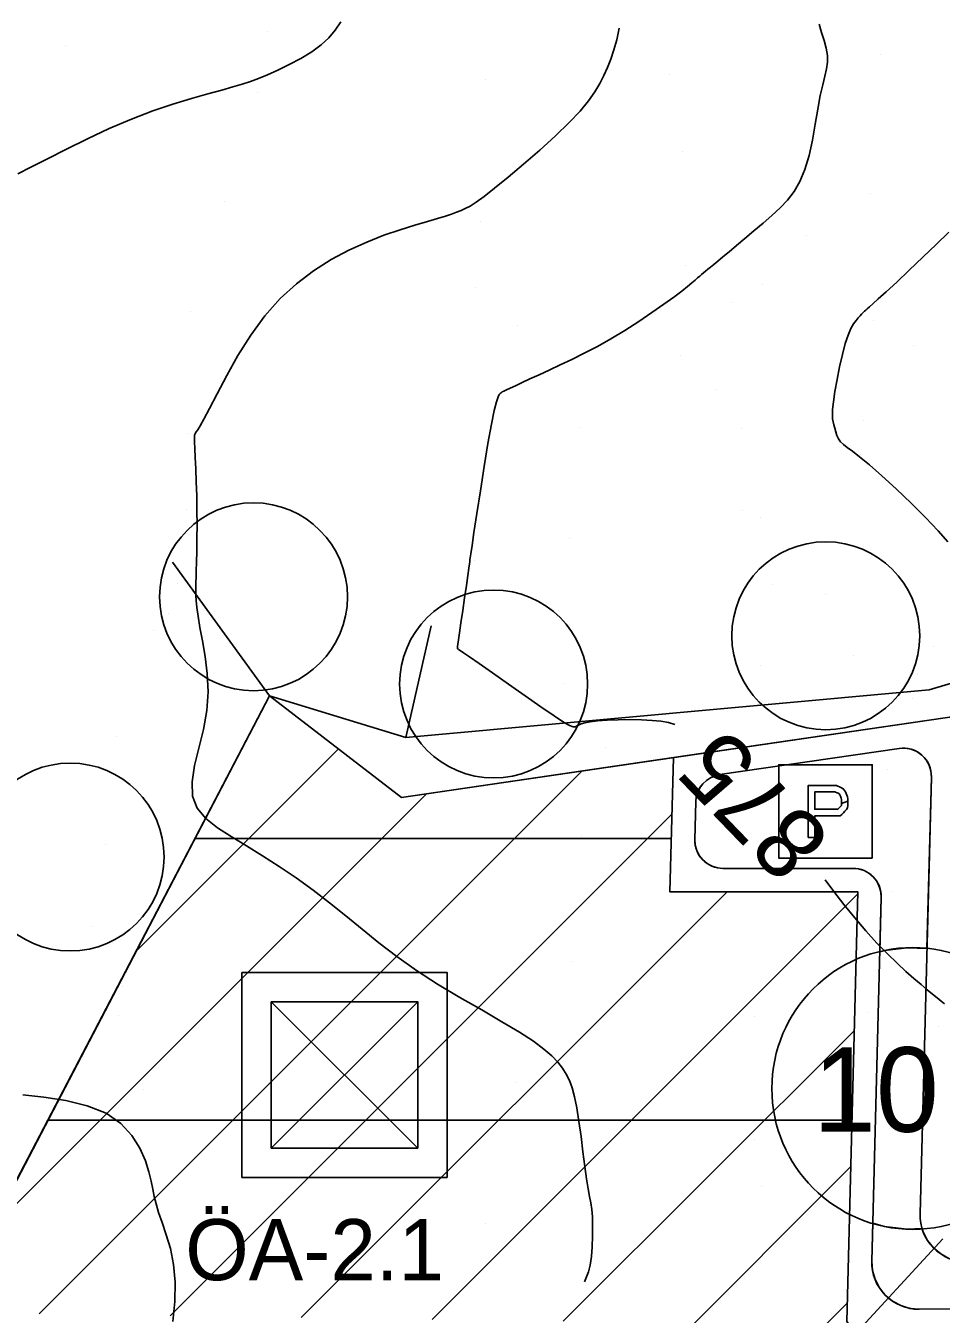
# Model space of a CAD drawing. Extents: x 400243 to 403697, y 4403637 to 4408083.
# Drawn here: x 402609.9 to 402707.4, y 4406077.2 to 4406214.4 of the extents above; entities that cross this region are included whole.
import ezdxf

# ---------------------------------------------------------------- set-up
doc = ezdxf.new("R2010")
doc.units = 0
for name, color, linetype in [('ADAKENARI', 7, 'Continuous'), ('HH_IC', 7, 'Continuous'), ('KALDIRIM', 7, 'Continuous'), ('PL_GES', 7, 'Continuous'), ('PL_YAZI', 7, 'Continuous'), ('PL_YOL', 7, 'Continuous'), ('SM_DAIRE', 7, 'Continuous'), ('SM_SEMBOL', 7, 'Continuous'), ('SM_YGEN', 7, 'Continuous'), ('SNR_MULKIYET', 7, 'Continuous'), ('SNR_ONAMA', 7, 'Continuous'), ('SNR_SEMBOL', 7, 'Continuous'), ('TR_GES', 7, 'Continuous')]:
    doc.layers.add(name, color=color, linetype=linetype)

msp = doc.modelspace()

# ---------------------------------------------------------------- linework, layer by layer
at = {"layer": 'ADAKENARI'}
for p, q in [((402560.49, 4405998.76), (402635.88, 4406143.05)), ((402635.88, 4406143.05), (402649.95, 4406132.25)), ((402678.87, 4406136.48), (402709, 4406140.88)), ((402649.95, 4406132.25), (402678.87, 4406136.48)), ((402678.87, 4406136.48), (402678.5, 4406122.19)), ((402678.5, 4406122.19), (402698.51, 4406122.19)), ((402698.51, 4406122.19), (402697.33, 4406076.45))]:
    msp.add_line(p, q, dxfattribs=at)
at = {"layer": 'HH_IC'}
for p, q in [((402635.66, 4406213.79), (402635.66, 4406213.79)), ((402614.19, 4406212.31), (402614.19, 4406212.31)), ((402700.92, 4406211.39), (402700.92, 4406211.39)), ((402658.88, 4406208.7), (402658.88, 4406208.7)), ((402678.51, 4406209.24), (402678.51, 4406209.24)), ((402634.62, 4406207.26), (402634.62, 4406207.26)), ((402679.87, 4406201), (402679.87, 4406201)), ((402699.88, 4406196.49), (402699.88, 4406196.49)), ((402631.11, 4406195.7), (402631.11, 4406195.7)), ((402658.31, 4406193.53), (402658.31, 4406193.53)), ((402693.03, 4406192.06), (402693.03, 4406192.06)), ((402680.15, 4406188.84), (402680.15, 4406188.84)), ((402688.4, 4406186.9), (402688.4, 4406186.9)), ((402657.78, 4406186.51), (402657.78, 4406186.51)), ((402627.45, 4406183.96), (402627.45, 4406183.96)), ((402685.09, 4406184.9), (402685.09, 4406184.9)), ((402700.19, 4406183.01), (402700.19, 4406183.01)), ((402662.24, 4406182.45), (402662.24, 4406182.45)), ((402704.38, 4406180.41), (402704.38, 4406180.41)), ((402679.59, 4406179.28), (402679.59, 4406179.28)), ((402660.65, 4406174.81), (402660.65, 4406174.81)), ((402683.48, 4406175.67), (402683.48, 4406175.67)), ((402669.02, 4406171.6), (402669.02, 4406171.6)), ((402699.11, 4406172.34), (402699.11, 4406172.34)), ((402627.31, 4406170.94), (402627.31, 4406170.94)), ((402686.1, 4406171.54), (402686.1, 4406171.54)), ((402627.02, 4406162.93), (402627.02, 4406162.93)), ((402686.28, 4406162.75), (402686.28, 4406162.75)), ((402688.19, 4406162.1), (402688.19, 4406162.1)), ((402667.84, 4406159.77), (402667.84, 4406159.77)), ((402657.67, 4406157.43), (402657.67, 4406157.43)), ((402626.06, 4406155.05), (402626.06, 4406155.05)), ((402689.4, 4406154.94), (402689.4, 4406154.94)), ((402695.11, 4406153.89), (402695.11, 4406153.89)), ((402625.18, 4406151.84), (402625.18, 4406151.84)), ((402623.55, 4406150.06), (402623.55, 4406150.06)), ((402706.57, 4406148.32), (402706.57, 4406148.32)), ((402656.08, 4406148.2), (402656.08, 4406148.2)), ((402698.07, 4406147.37), (402698.07, 4406147.37)), ((402688.15, 4406146.3), (402688.15, 4406146.3)), ((402667.24, 4406144.39), (402667.24, 4406144.39)), ((402704.88, 4406145.3), (402704.88, 4406145.3)), ((402704.32, 4406142.82), (402704.32, 4406142.82)), ((402689.66, 4406142.33), (402689.66, 4406142.33)), ((402619.62, 4406138.75), (402619.62, 4406138.75)), ((402668.07, 4406139.97), (402668.07, 4406139.97)), ((402671.7, 4406137.54), (402671.7, 4406137.54)), ((402690.86, 4406135.65), (402690.86, 4406135.65)), ((402701.68, 4406135.24), (402701.68, 4406135.24)), ((402669.04, 4406128.11), (402669.04, 4406128.11)), ((402618.41, 4406127.28), (402618.41, 4406127.28)), ((402689.5, 4406125.46), (402689.5, 4406125.46)), ((402702.05, 4406122.2), (402702.05, 4406122.2)), ((402616.97, 4406118.46), (402616.97, 4406118.46)), ((402668.06, 4406114.78), (402668.06, 4406114.78)), ((402620.2, 4406112.09), (402620.2, 4406112.09)), ((402619.87, 4406109.06), (402619.87, 4406109.06)), ((402687.46, 4406108.95), (402687.46, 4406108.95)), ((402699.51, 4406109.33), (402699.51, 4406109.33)), ((402707.11, 4406107.84), (402707.11, 4406107.84)), ((402662.12, 4406101.95), (402662.12, 4406101.95)), ((402622.46, 4406101.16), (402622.46, 4406101.16)), ((402687.52, 4406095.78), (402687.52, 4406095.78)), ((402705.6, 4406095.41), (402705.6, 4406095.41)), ((402625.36, 4406091.26), (402625.36, 4406091.26)), ((402688.23, 4406090.81), (402688.23, 4406090.81)), ((402658.83, 4406086.89), (402658.83, 4406086.89)), ((402705.48, 4406084.27), (402705.48, 4406084.27)), ((402628.32, 4406082.21), (402628.32, 4406082.21))]:
    msp.add_line(p, q, dxfattribs=at)
for points in [[(402609.09, 4406198.63), (402610.5, 4406199.34), (402612.25, 4406200.24), (402614.28, 4406201.27), (402616.51, 4406202.37), (402618.84, 4406203.47), (402621.19, 4406204.47), (402623.46, 4406205.34), (402625.6, 4406206.07), (402627.57, 4406206.67), (402629.32, 4406207.16), (402630.8, 4406207.56), (402632, 4406207.89), (402632.98, 4406208.18), (402633.85, 4406208.47), (402634.71, 4406208.79), (402635.66, 4406209.18), (402636.77, 4406209.67), (402637.99, 4406210.26), (402639.22, 4406210.91), (402640.39, 4406211.62), (402641.4, 4406212.36), (402642.21, 4406213.12), (402642.87, 4406213.94), (402643.49, 4406214.83)], [(402669.42, 4406080.69), (402669.64, 4406081.19), (402669.84, 4406081.74), (402670.02, 4406082.45), (402670.15, 4406083.36), (402670.24, 4406084.41), (402670.28, 4406085.53), (402670.28, 4406086.61), (402670.25, 4406087.58), (402670.18, 4406088.37), (402670.07, 4406089.07), (402669.94, 4406089.77), (402669.79, 4406090.59), (402669.62, 4406091.64), (402669.44, 4406092.97), (402669.24, 4406094.52), (402669.04, 4406096.15), (402668.82, 4406097.75), (402668.59, 4406099.19), (402668.36, 4406100.37), (402668.1, 4406101.32), (402667.8, 4406102.11), (402667.46, 4406102.79), (402667.06, 4406103.42), (402666.57, 4406104.05), (402665.95, 4406104.72), (402665.1, 4406105.45), (402663.98, 4406106.29), (402662.5, 4406107.25), (402660.63, 4406108.37), (402658.47, 4406109.62), (402656.14, 4406110.96), (402653.78, 4406112.38), (402651.52, 4406113.83), (402649.44, 4406115.3), (402647.54, 4406116.76), (402645.75, 4406118.21), (402644.02, 4406119.64), (402642.29, 4406121.03), (402640.52, 4406122.38), (402638.73, 4406123.67), (402636.93, 4406124.89), (402635.16, 4406126.04), (402633.44, 4406127.1), (402631.81, 4406128.07), (402630.34, 4406129.01), (402629.1, 4406130), (402628.2, 4406131.09), (402627.69, 4406132.38), (402627.64, 4406133.9), (402627.92, 4406135.63), (402628.38, 4406137.5), (402628.87, 4406139.48), (402629.23, 4406141.49), (402629.35, 4406143.5), (402629.26, 4406145.44), (402629.04, 4406147.26), (402628.75, 4406148.92), (402628.48, 4406150.35), (402628.29, 4406151.53), (402628.16, 4406152.46), (402628.08, 4406153.2), (402628.05, 4406153.76), (402628.04, 4406154.19), (402628.04, 4406154.52), (402628.04, 4406154.83), (402628.06, 4406155.19), (402628.08, 4406155.67), (402628.1, 4406156.36), (402628.13, 4406157.3), (402628.15, 4406158.46), (402628.17, 4406159.8), (402628.18, 4406161.26), (402628.17, 4406162.79), (402628.14, 4406164.34), (402628.09, 4406165.84), (402628.04, 4406167.23), (402627.98, 4406168.44), (402627.94, 4406169.41), (402627.92, 4406170.1), (402627.91, 4406170.55), (402627.92, 4406170.81), (402627.96, 4406170.96), (402628.02, 4406171.05), (402628.1, 4406171.16), (402628.25, 4406171.38), (402628.51, 4406171.8), (402628.91, 4406172.53), (402629.5, 4406173.65), (402630.31, 4406175.23), (402631.33, 4406177.16), (402632.53, 4406179.29), (402633.89, 4406181.45), (402635.4, 4406183.52), (402637.04, 4406185.35), (402638.77, 4406186.94), (402640.58, 4406188.32), (402642.44, 4406189.51), (402644.33, 4406190.52), (402646.23, 4406191.37), (402648.07, 4406192.09), (402649.8, 4406192.68), (402651.37, 4406193.17), (402652.7, 4406193.56), (402653.77, 4406193.88), (402654.61, 4406194.13), (402655.27, 4406194.35), (402655.8, 4406194.54), (402656.27, 4406194.73), (402656.72, 4406194.93), (402657.24, 4406195.21), (402657.88, 4406195.63), (402658.72, 4406196.24), (402659.84, 4406197.12), (402661.28, 4406198.28), (402662.93, 4406199.67), (402664.65, 4406201.17), (402666.31, 4406202.68), (402667.78, 4406204.09), (402668.95, 4406205.32), (402669.84, 4406206.4), (402670.52, 4406207.35), (402671.05, 4406208.24), (402671.48, 4406209.09), (402671.87, 4406209.95), (402672.22, 4406210.85), (402672.55, 4406211.83), (402672.84, 4406212.91), (402673.11, 4406214.13)], [(402679.04, 4406140), (402678.35, 4406140.21), (402677.55, 4406140.36), (402676.61, 4406140.45), (402675.49, 4406140.51), (402674.26, 4406140.53), (402673.01, 4406140.52), (402671.83, 4406140.48), (402670.81, 4406140.41), (402670.03, 4406140.31), (402669.45, 4406140.19), (402669.04, 4406140.07), (402668.76, 4406139.95), (402668.57, 4406139.84), (402668.41, 4406139.75), (402668.19, 4406139.75), (402667.82, 4406139.9), (402667.18, 4406140.27), (402666.19, 4406140.92), (402664.78, 4406141.88), (402663.09, 4406143.05), (402661.31, 4406144.3), (402659.61, 4406145.5), (402658.19, 4406146.5), (402657.18, 4406147.21), (402656.54, 4406147.65), (402656.18, 4406147.9), (402656.01, 4406148.01), (402655.95, 4406148.05), (402655.91, 4406148.08), (402655.9, 4406148.1), (402655.89, 4406148.12), (402655.89, 4406148.13), (402655.89, 4406148.15), (402655.89, 4406148.16), (402655.89, 4406148.18), (402655.89, 4406148.19), (402655.89, 4406148.2), (402655.89, 4406148.21), (402655.89, 4406148.23), (402655.9, 4406148.32), (402655.93, 4406148.56), (402656, 4406149.01), (402656.11, 4406149.76), (402656.26, 4406150.84), (402656.45, 4406152.13), (402656.65, 4406153.51), (402656.84, 4406154.81), (402657, 4406155.89), (402657.11, 4406156.65), (402657.17, 4406157.12), (402657.21, 4406157.37), (402657.22, 4406157.48), (402657.22, 4406157.51), (402657.22, 4406157.56), (402657.25, 4406157.74), (402657.31, 4406158.19), (402657.44, 4406159.05), (402657.65, 4406160.46), (402657.96, 4406162.47), (402658.33, 4406164.9), (402658.74, 4406167.47), (402659.14, 4406169.91), (402659.5, 4406171.97), (402659.8, 4406173.43), (402660.03, 4406174.36), (402660.21, 4406174.89), (402660.34, 4406175.15), (402660.45, 4406175.26), (402660.55, 4406175.33), (402660.66, 4406175.41), (402660.83, 4406175.5), (402661.1, 4406175.63), (402661.5, 4406175.82), (402662.06, 4406176.08), (402662.77, 4406176.42), (402663.61, 4406176.81), (402664.58, 4406177.25), (402665.66, 4406177.75), (402666.82, 4406178.29), (402668.07, 4406178.88), (402669.39, 4406179.53), (402670.78, 4406180.26), (402672.22, 4406181.07), (402673.71, 4406181.97), (402675.18, 4406182.92), (402676.58, 4406183.86), (402677.85, 4406184.75), (402678.93, 4406185.52), (402679.76, 4406186.15), (402680.39, 4406186.64), (402680.85, 4406187.02), (402681.18, 4406187.31), (402681.44, 4406187.55), (402681.67, 4406187.75), (402681.87, 4406187.92), (402682.07, 4406188.09), (402682.29, 4406188.27), (402682.53, 4406188.47), (402682.82, 4406188.71), (402683.16, 4406189), (402683.6, 4406189.35), (402684.13, 4406189.8), (402684.8, 4406190.34), (402685.59, 4406191), (402686.49, 4406191.75), (402687.44, 4406192.55), (402688.41, 4406193.38), (402689.35, 4406194.2), (402690.22, 4406195.01), (402691.01, 4406195.84), (402691.72, 4406196.76), (402692.34, 4406197.82), (402692.87, 4406199.08), (402693.31, 4406200.58), (402693.67, 4406202.23), (402693.97, 4406203.92), (402694.25, 4406205.53), (402694.5, 4406206.96), (402694.76, 4406208.11), (402694.99, 4406209.04), (402695.18, 4406209.82), (402695.28, 4406210.52), (402695.27, 4406211.23), (402695.14, 4406212.01), (402694.92, 4406212.83), (402694.65, 4406213.7), (402694.39, 4406214.58)], [(402708.09, 4406159.44), (402707.04, 4406160.63), (402705.7, 4406162.04), (402704.17, 4406163.56), (402702.59, 4406165.09), (402701.07, 4406166.49), (402699.74, 4406167.66), (402698.69, 4406168.52), (402697.92, 4406169.1), (402697.36, 4406169.5), (402696.96, 4406169.81), (402696.67, 4406170.09), (402696.45, 4406170.42), (402696.28, 4406170.79), (402696.15, 4406171.18), (402696.04, 4406171.56), (402695.96, 4406171.92), (402695.88, 4406172.23), (402695.82, 4406172.56), (402695.79, 4406172.98), (402695.81, 4406173.56), (402695.9, 4406174.37), (402696.06, 4406175.46), (402696.29, 4406176.74), (402696.56, 4406178.09), (402696.86, 4406179.4), (402697.17, 4406180.56), (402697.48, 4406181.47), (402697.77, 4406182.16), (402698.05, 4406182.67), (402698.31, 4406183.03), (402698.54, 4406183.31), (402698.74, 4406183.53), (402698.91, 4406183.71), (402699.06, 4406183.86), (402699.21, 4406184), (402699.35, 4406184.13), (402699.51, 4406184.27), (402699.75, 4406184.47), (402700.11, 4406184.8), (402700.68, 4406185.32), (402701.51, 4406186.08), (402702.64, 4406187.12), (402703.98, 4406188.38), (402705.42, 4406189.75), (402706.85, 4406191.13), (402708.17, 4406192.43)], [(402707.74, 4406110.28), (402707.36, 4406110.56), (402706.94, 4406110.9), (402706.45, 4406111.3), (402705.88, 4406111.77), (402705.23, 4406112.32), (402704.47, 4406112.97), (402703.62, 4406113.72), (402702.68, 4406114.59), (402701.65, 4406115.59), (402700.54, 4406116.74), (402699.36, 4406118.04), (402698.17, 4406119.44), (402697.01, 4406120.85), (402695.94, 4406122.22), (402695.01, 4406123.48)], [(402625.61, 4406076.44), (402625.82, 4406078.58), (402625.86, 4406080.64), (402625.68, 4406082.52), (402625.34, 4406084.21), (402624.9, 4406085.69), (402624.45, 4406086.98), (402624.07, 4406088.07), (402623.81, 4406088.98), (402623.63, 4406089.77), (402623.48, 4406090.54), (402623.31, 4406091.38), (402623.06, 4406092.37), (402622.68, 4406093.57), (402622.1, 4406094.91), (402621.25, 4406096.27), (402620.07, 4406097.54), (402618.49, 4406098.62), (402616.49, 4406099.42), (402614.22, 4406099.98), (402611.87, 4406100.34), (402609.62, 4406100.57)]]:
    msp.add_lwpolyline(points, dxfattribs=at)
at = {"layer": 'KALDIRIM'}
for p, q in [((402683.82, 4406134.68), (402702.89, 4406137.47)), ((402706.33, 4406134.42), (402705.13, 4406087.92)), ((402681.25, 4406131.79), (402681.15, 4406127.77)), ((402684.15, 4406124.69), (402698, 4406124.69)), ((402700.99, 4406121.61), (402699.99, 4406082.89)), ((402705.02, 4406077.76), (402714.5, 4406077.81))]:
    msp.add_line(p, q, dxfattribs=at)
for centre, radius, start, end in [((402703.33, 4406134.5), 3, 358.5191, 98.3146), ((402684.25, 4406131.71), 3, 98.3146, 178.5191), ((402684.15, 4406127.69), 3, 178.5191, 270), ((402698, 4406121.69), 3, 358.5191, 90), ((402710.12, 4406087.79), 5, 178.5191, 270.3201), ((402704.99, 4406082.76), 5, 178.5191, 270.3201)]:
    msp.add_arc(centre, radius, start, end, dxfattribs=at)
at = {"layer": 'PL_GES'}
msp.add_lwpolyline([(402649.95, 4406132.25), (402678.87, 4406136.48), (402678.5, 4406122.19), (402698.51, 4406122.19), (402697.33, 4406076.45), (402698.29, 4406075.22), (402609.95, 4405979.43), (402560.49, 4405998.76), (402635.88, 4406143.05)], close=True, dxfattribs=at)
at = {"layer": 'PL_YOL'}
for points in [[(402706.27, 4406135.07), (402706.08, 4406135.69), (402705.76, 4406136.26), (402705.32, 4406136.74), (402704.79, 4406137.12), (402704.19, 4406137.37), (402703.55, 4406137.49), (402702.89, 4406137.47), (402683.82, 4406134.68), (402683.31, 4406134.56), (402682.82, 4406134.35), (402682.39, 4406134.06), (402682.01, 4406133.7), (402681.69, 4406133.28), (402681.46, 4406132.81), (402681.31, 4406132.31), (402681.25, 4406131.79), (402681.15, 4406127.77), (402681.19, 4406127.17), (402681.35, 4406126.6), (402681.63, 4406126.06), (402682, 4406125.6), (402682.46, 4406125.21), (402682.98, 4406124.93), (402683.55, 4406124.75), (402684.15, 4406124.69), (402698, 4406124.69), (402698.59, 4406124.63), (402699.16, 4406124.45), (402699.69, 4406124.17), (402700.14, 4406123.78), (402700.52, 4406123.32), (402700.79, 4406122.78), (402700.95, 4406122.21), (402700.99, 4406121.61), (402700.84, 4406115.82), (402701.35, 4406115.96), (402703.74, 4406116.25), (402705.86, 4406116.17), (402706.33, 4406134.42)], [(402710.15, 4406082.79), (402709.16, 4406082.88), (402708.2, 4406083.17), (402707.32, 4406083.65), (402706.55, 4406084.29), (402705.93, 4406085.07), (402705.47, 4406085.96), (402705.36, 4406086.34), (402703.74, 4406086.28), (402701.35, 4406086.57), (402700.1, 4406086.93), (402699.99, 4406082.89), (402700.07, 4406081.89), (402700.34, 4406080.93), (402700.8, 4406080.04), (402701.42, 4406079.26), (402702.19, 4406078.62), (402703.07, 4406078.14), (402704.02, 4406077.85), (402705.02, 4406077.76), (402714.5, 4406077.81), (402714.53, 4406082.81)]]:
    msp.add_lwpolyline(points, close=True, dxfattribs=at)
at = {"layer": 'SM_DAIRE'}
msp.add_circle((402704.35, 4406101.26), 15, dxfattribs=at)
at = {"layer": 'SM_SEMBOL'}
for points in [[(402700.04, 4406125.78), (402690.09, 4406125.78), (402690.09, 4406135.73), (402700.04, 4406135.73)], [(402697.44, 4406131.85), (402697.43, 4406132.09), (402697.4, 4406132.31), (402697.34, 4406132.5), (402697.26, 4406132.68), (402697.18, 4406132.85), (402697.09, 4406133), (402696.98, 4406133.14), (402696.84, 4406133.24), (402696.69, 4406133.32), (402696.54, 4406133.39), (402696.38, 4406133.45), (402696.22, 4406133.52), (402695.99, 4406133.52), (402693.22, 4406133.52), (402693.22, 4406127.99), (402693.91, 4406127.99), (402693.91, 4406130.27), (402696.62, 4406130.27), (402696.8, 4406130.44), (402696.96, 4406130.61), (402697.13, 4406130.78), (402697.28, 4406130.96), (402697.4, 4406131.15), (402697.44, 4406131.37), (402697.45, 4406131.61), (402697.44, 4406131.85), (402696.76, 4406131.61), (402696.76, 4406131.46), (402696.75, 4406131.4), (402696.72, 4406131.36), (402696.62, 4406131.24), (402696.47, 4406131.09), (402696.38, 4406130.99), (402693.91, 4406130.99), (402693.91, 4406132.83), (402696.09, 4406132.83), (402696.11, 4406132.82), (402696.3, 4406132.75), (402696.4, 4406132.7), (402696.48, 4406132.65), (402696.5, 4406132.64), (402696.52, 4406132.62), (402696.57, 4406132.52), (402696.64, 4406132.39), (402696.69, 4406132.26), (402696.72, 4406132.16), (402696.75, 4406132.01), (402696.76, 4406131.82), (402696.76, 4406131.61)]]:
    msp.add_lwpolyline(points, close=True, dxfattribs=at)
at = {"layer": 'SNR_MULKIYET'}
for p, q in [((402635.88, 4406143.05), (402625.57, 4406157.3)), ((402706.08, 4406143.71), (402732.2, 4406151.43)), ((402653.11, 4406150.53), (402650.41, 4406138.62)), ((402635.88, 4406143.05), (402560.49, 4405998.76)), ((402635.88, 4406143.05), (402650.41, 4406138.62)), ((402649.95, 4406132.25), (402635.88, 4406143.05)), ((402650.41, 4406138.62), (402706.08, 4406143.71)), ((402709, 4406140.88), (402649.95, 4406132.25)), ((402609.95, 4405979.43), (402707.56, 4406085.27))]:
    msp.add_line(p, q, dxfattribs=at)
at = {"layer": 'SNR_ONAMA'}
for centre in [(402634.19, 4406153.61), (402695.09, 4406149.46), (402659.74, 4406144.32), (402614.67, 4406125.9)]:
    msp.add_circle(centre, 10, dxfattribs=at)
at = {"layer": 'SNR_SEMBOL'}
for p, q in [((402651.66, 4406110.5), (402636.07, 4406094.92)), ((402636.07, 4406110.5), (402651.66, 4406094.92))]:
    msp.add_line(p, q, dxfattribs=at)
for points in [[(402632.96, 4406113.62), (402632.96, 4406091.8), (402654.78, 4406091.8), (402654.78, 4406113.62)], [(402636.07, 4406110.5), (402636.07, 4406094.92), (402651.66, 4406094.92), (402651.66, 4406110.5)]]:
    msp.add_lwpolyline(points, close=True, dxfattribs=at)
at = {"layer": 'TR_GES'}
for p, q in [((402621.66, 4406115.84), (402643.23, 4406137.41)), ((402611.36, 4406077.26), (402669.17, 4406135.06)), ((402606.19, 4406086.22), (402652.61, 4406132.64)), ((402625.31, 4406077.06), (402678.72, 4406130.47)), ((402627.95, 4406127.88), (402678.65, 4406127.88)), ((402639.26, 4406076.87), (402684.58, 4406122.19)), ((402653.21, 4406076.67), (402698.5, 4406121.97)), ((402667.15, 4406076.48), (402698.13, 4406107.45)), ((402612.28, 4406097.88), (402697.88, 4406097.88)), ((402652.58, 4406047.77), (402697.75, 4406092.94)), ((402601.64, 4405982.68), (402697.38, 4406078.42))]:
    msp.add_line(p, q, dxfattribs=at)

# ---------------------------------------------------------------- texts
at = {"layer": 'HH_IC'}
msp.add_text('875', height=7.5, rotation=134.013, dxfattribs=at).set_placement((402695.91, 4406127.94))
at = {"layer": 'PL_YAZI'}
msp.add_text('ÖA-2.1', height=6.5, rotation=0, dxfattribs=at).set_placement((402626.92, 4406080.85))
at = {"layer": 'SM_YGEN'}
msp.add_text('10', height=9, dxfattribs=at).set_placement((402693.74, 4406096.65))

doc.saveas('drawing.dxf')
